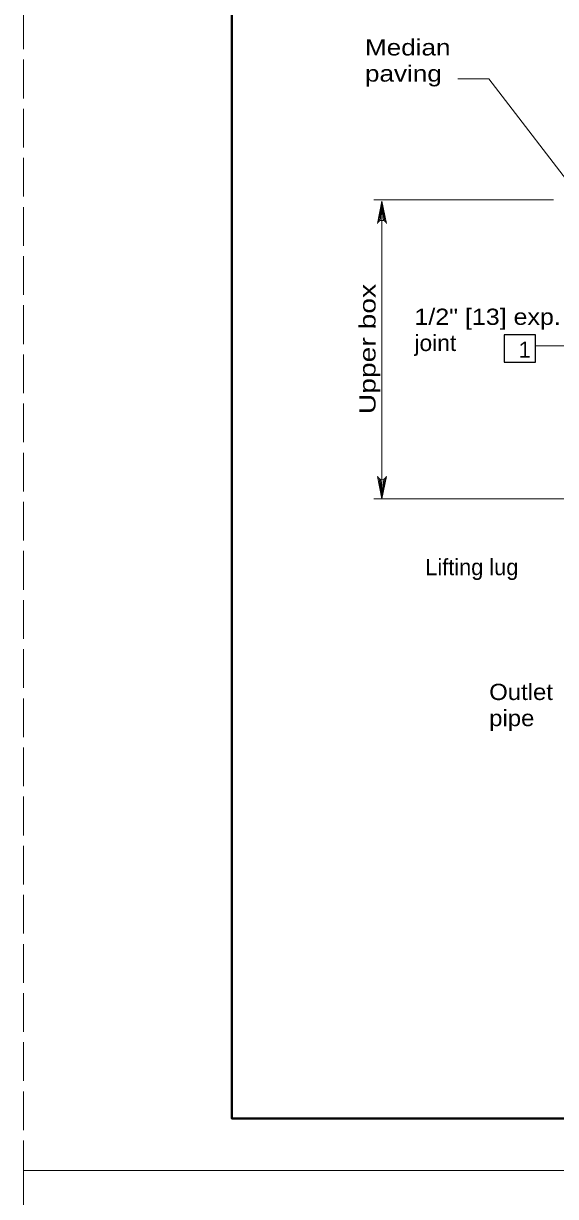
# Model space of a CAD drawing. Extents: x 339.1 to 373.1, y 1412.7 to 1456.7.
# Drawn here: x 339.06 to 344.17, y 1434.5 to 1445.77 of the extents above; entities that cross this region are included whole.
import ezdxf

# ---------------------------------------------------------------- set-up
doc = ezdxf.new("R2010")
doc.units = 0
doc.header["$LTSCALE"] = 0.062
doc.linetypes.add('LONG_DASHED', pattern=[7.5, 6, -1.5])
doc.layers.add('1', color=7, linetype='Continuous', lineweight=13)

msp = doc.modelspace()

# ---------------------------------------------------------------- linework, layer by layer
at = {"layer": '1'}
for p, q in [((344.15042, 1444.07167), (342.42408, 1444.07167)), ((342.47275, 1443.86275), (342.50275, 1444.05892)), ((342.48533, 1443.87017), (342.50275, 1444.05892)), ((342.50275, 1444.05892), (342.50275, 1441.19975)), ((342.50275, 1443.87358), (342.50275, 1444.05892)), ((342.51642, 1443.87158), (342.50275, 1444.05892)), ((342.52983, 1443.865), (342.50275, 1444.05892)), ((342.47558, 1441.39358), (342.50275, 1441.19975)), ((342.489, 1441.38708), (342.50275, 1441.19975)), ((342.53275, 1441.39592), (342.50275, 1441.19975)), ((342.52017, 1441.3885), (342.50275, 1441.19975)), ((342.50275, 1441.38508), (342.50275, 1441.19975)), ((345.13775, 1441.19975), (342.42408, 1441.19975))]:
    msp.add_line(p, q, dxfattribs=at)
at = {"layer": '1', "linetype": 'LONG_DASHED'}
for points in [[(339.0605, 1434.7455), (373.0605, 1434.7455), (373.0605, 1456.7455), (339.0605, 1456.7455)], [(339.0605, 1412.7455), (373.0605, 1412.7455), (373.0605, 1434.7455), (339.0605, 1434.7455)]]:
    msp.add_lwpolyline(points, close=True, dxfattribs=at)
at = {"layer": '1', "lineweight": 25}
msp.add_lwpolyline([(372.5605, 1435.2455), (341.0605, 1435.2455), (341.0605, 1456.2455)], dxfattribs=at)
at = {"layer": '1', "lineweight": 40}
msp.add_lwpolyline([(341.0605, 1456.2455), (372.5605, 1456.2455), (372.5605, 1435.2455), (341.0605, 1435.2455)], close=True, dxfattribs=at)
at = {"layer": '1'}
for points in [[(344.43375, 1444.056), (343.529, 1445.23283), (343.23208, 1445.23283)], [(342.45992, 1443.84475), (342.50275, 1444.05892), (342.54558, 1443.84475)], [(345.17733, 1443.35625), (344.61408, 1442.66708), (343.97542, 1442.66708)], [(342.54558, 1441.41392), (342.50275, 1441.19975), (342.45992, 1441.41392)]]:
    msp.add_lwpolyline(points, dxfattribs=at)
at = {"layer": '1', "lineweight": 25}
msp.add_lwpolyline([(343.67675, 1442.77258), (343.67675, 1442.511), (343.97542, 1442.511), (343.97542, 1442.77258)], close=True, dxfattribs=at)
at = {"layer": '1'}
for centre, start, end in [((342.50279, 1443.82745), 22.08782, 157.91395), ((342.5027, 1441.43119), 202.08782, 337.91395)]:
    msp.add_arc(centre, 0.04623, start, end, dxfattribs=at)

# ---------------------------------------------------------------- texts
for s, width, p in [('Median', 1.2, (342.33958, 1445.45767)), ('paving', 1.2, (342.33958, 1445.2065)), ('1/2" [13] exp.', 1.15, (342.81417, 1442.86958)), ('joint', 1.05, (342.81417, 1442.61842)), ('Outlet', 1.1, (343.53217, 1439.2655)), ('pipe', 1.1, (343.53217, 1439.01433))]:
    msp.add_text(s, height=0.156, dxfattribs=dict(at, width=width)).set_placement(p)
at = {"layer": '1', "width": 1.3}
msp.add_text('Upper box', height=0.156, rotation=90, dxfattribs=at).set_placement((342.44108, 1442.01225))
at = {"layer": '1'}
for s, p in [('1', (343.81558, 1442.5535)), ('Lifting lug', (342.91883, 1440.46492))]:
    msp.add_text(s, height=0.156, dxfattribs=at).set_placement(p)

doc.saveas('drawing.dxf')
